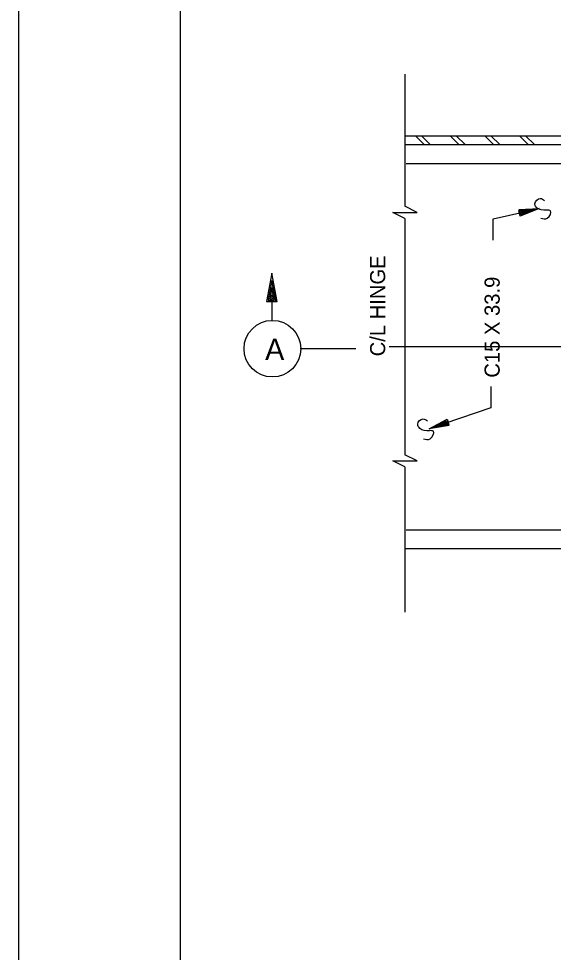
# Model space of a CAD drawing. Extents: x 0.1 to 13.5, y 0.1 to 9.5.
# Drawn here: x 0.124 to 1.776, y 4.152 to 7.04 of the extents above; entities that cross this region are included whole.
import ezdxf

# ---------------------------------------------------------------- set-up
doc = ezdxf.new("R2010")
doc.units = 0
for name, color, linetype in [('Level 1', 7, 'Continuous'), ('Level 13', 7, 'Continuous'), ('Level 2', 7, 'Continuous'), ('Level 25', 7, 'Continuous'), ('Level 3', 7, 'Continuous')]:
    doc.layers.add(name, color=color, linetype=linetype)

msp = doc.modelspace()

# ---------------------------------------------------------------- linework, layer by layer
at = {"layer": 'Level 1'}
for points in [[(0.1238, 9.4569), (13.4571, 9.4569), (13.4571, 0.1236), (0.1238, 0.1236)], [(0.6238, 9.2903), (13.2904, 9.2903), (13.2904, 0.2903), (0.6238, 0.2903)]]:
    msp.add_lwpolyline(points, close=True, dxfattribs=at)
at = {"layer": 'Level 13'}
for points in [[(1.3175, 6.4222), (1.28, 6.4408), (1.355, 6.4408), (1.3175, 6.4596)], [(1.3175, 5.6538), (1.28, 5.6724), (1.355, 5.6724), (1.3175, 5.6911)]]:
    msp.add_lwpolyline(points, dxfattribs=at)
at = {"layer": 'Level 2'}
for p, q in [((1.3769, 6.6506), (1.3508, 6.6766)), ((1.3957, 6.6506), (1.3697, 6.6766)), ((1.4841, 6.6506), (1.4581, 6.6766)), ((1.503, 6.6506), (1.4769, 6.6766)), ((1.5914, 6.6506), (1.5653, 6.6766)), ((1.6102, 6.6506), (1.5842, 6.6766)), ((1.6986, 6.6506), (1.6726, 6.6766)), ((1.7175, 6.6506), (1.6914, 6.6766)), ((1.2683, 6.0256), (5.4335, 6.0256))]:
    msp.add_line(p, q, dxfattribs=at)
at = {"layer": 'Level 25'}
for p, q in [((1.3175, 6.8684), (1.3175, 6.4596)), ((2.6271, 6.6766), (1.3175, 6.6766)), ((1.3175, 6.6506), (2.6479, 6.6506)), ((1.3216, 6.5922), (2.5646, 6.5922)), ((1.3175, 6.4222), (1.3175, 5.6911)), ((1.3175, 5.6538), (1.3175, 5.2038)), ((1.3216, 5.459), (2.5646, 5.459)), ((1.3175, 5.4006), (2.6479, 5.4006))]:
    msp.add_line(p, q, dxfattribs=at)
for points in [[(1.7372, 6.4228), (1.7571, 6.4228), (1.7671, 6.4461), (1.7554, 6.4478), (1.7255, 6.4544), (1.7189, 6.4677), (1.7355, 6.4843), (1.7488, 6.4777)], [(1.3752, 5.7406), (1.3952, 5.7406), (1.4052, 5.7639), (1.3935, 5.7655), (1.3636, 5.7722), (1.3569, 5.7855), (1.3735, 5.8021), (1.3868, 5.7955)]]:
    msp.add_spline(points, degree=3, dxfattribs=at)
at = {"layer": 'Level 3'}
for p, q in [((1.7152, 6.4495), (1.7152, 6.4495)), ((1.7321, 6.4534), (1.7321, 6.4534)), ((0.9061, 6.165), (0.9061, 6.1067)), ((1.1655, 6.0192), (0.9934, 6.0192)), ((1.392, 5.7712), (1.392, 5.7712)), ((1.4084, 5.7768), (1.4084, 5.7768))]:
    msp.add_line(p, q, dxfattribs=at)
for points in [[(1.5903, 6.3552), (1.5903, 6.4207), (1.7321, 6.4534)], [(1.6691, 6.4495), (1.7321, 6.4534), (1.6737, 6.4293), (1.6697, 6.4465), (1.7152, 6.4495), (1.6756, 6.4332), (1.673, 6.4442), (1.699, 6.4458), (1.6774, 6.437), (1.6764, 6.4416), (1.6821, 6.4419)], [(0.9183, 6.165), (0.9227, 6.165), (0.9061, 6.2525), (0.8897, 6.165), (0.9183, 6.165), (0.9064, 6.2302), (0.8947, 6.1692), (0.9135, 6.1692), (0.9064, 6.2082), (0.8998, 6.1733), (0.9086, 6.1733), (0.9064, 6.1858), (0.9048, 6.1775)], [(1.5829, 5.9022), (1.5829, 5.8367), (1.392, 5.7712)], [(1.4543, 5.7817), (1.392, 5.7712), (1.4476, 5.8012), (1.4533, 5.7845), (1.4084, 5.7768), (1.4462, 5.7972), (1.4498, 5.7865), (1.4241, 5.7822), (1.4447, 5.7932), (1.4462, 5.7888), (1.4405, 5.7879)]]:
    msp.add_lwpolyline(points, dxfattribs=at)
msp.add_circle((0.9077, 6.0192), 0.0875, dxfattribs=at)

# ---------------------------------------------------------------- texts
at = {"layer": 'Level 2'}
msp.add_text('C15 X 33.9', height=0.0467, rotation=90, dxfattribs=at).set_placement((1.6102, 5.9295))
at = {"layer": 'Level 3'}
msp.add_text('C/L HINGE', height=0.04667, rotation=90, dxfattribs=at).set_placement((1.2563, 5.9956))
msp.add_text('A', height=0.0667, dxfattribs=at).set_placement((0.8852, 5.9839))

doc.saveas('drawing.dxf')
